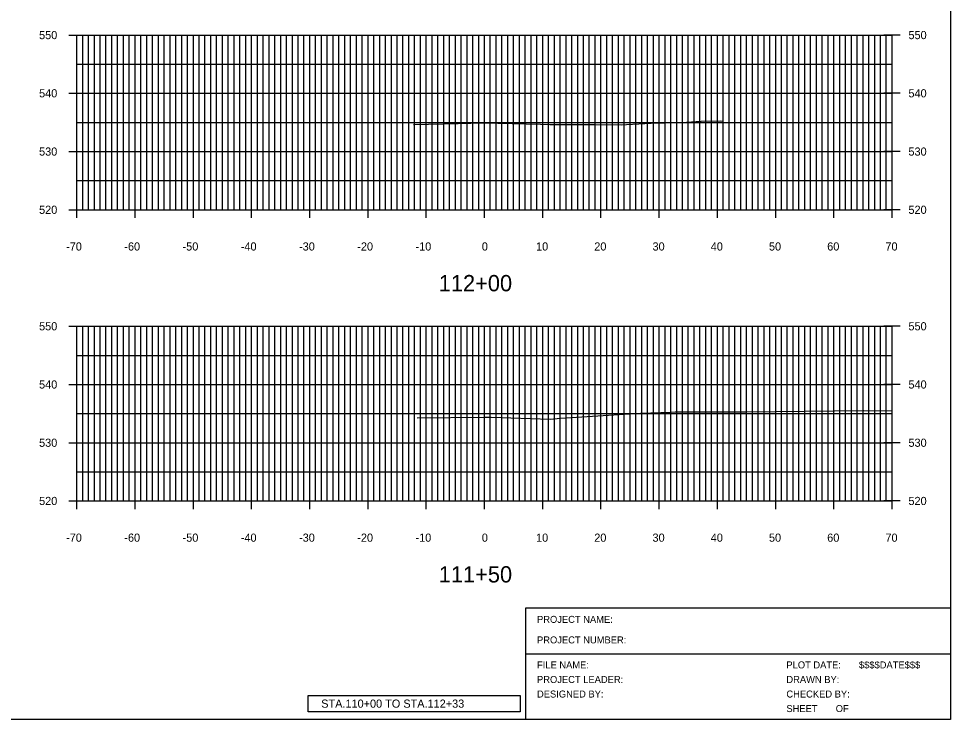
# Model space of a CAD drawing. Extents: x 1509063 to 1512863, y 401160 to 402918.
# Drawn here: x 1512702.7 to 1512862.7, y 402252.1 to 402372.4 of the extents above; entities that cross this region are included whole.
import ezdxf

# ---------------------------------------------------------------- set-up
doc = ezdxf.new("R2010")
doc.units = 0
for name, color, linetype in [('NBL1', 7, 'Continuous'), ('XAX_P', 7, 'Continuous'), ('XAXTIC_P', 7, 'Continuous'), ('XAXTXT_P_T', 7, 'Continuous'), ('XFRAME_P', 7, 'Continuous'), ('XGL_P', 7, 'Continuous'), ('XSLOG', 7, 'Continuous')]:
    doc.layers.add(name, color=color, linetype=linetype)

msp = doc.modelspace()

# ---------------------------------------------------------------- linework, layer by layer
at = {"layer": 'NBL1'}
for p, q in [((1512789.81, 402271.25), (1512862.73, 402271.25)), ((1512789.81, 402252.08), (1512789.81, 402271.25)), ((1512789.81, 402263.33), (1512862.73, 402263.33))]:
    msp.add_line(p, q, dxfattribs=at)
msp.add_lwpolyline([(1512862.73, 402252.08), (1512542.73, 402252.08), (1512542.73, 402462.08), (1512862.73, 402462.08)], close=True, dxfattribs=at)
at = {"layer": 'XAX_P'}
for p, q in [((1512712.73, 402339.58), (1512712.73, 402369.58)), ((1512782.73, 402339.58), (1512782.73, 402369.58)), ((1512852.73, 402339.58), (1512852.73, 402369.58)), ((1512712.73, 402339.58), (1512852.73, 402339.58)), ((1512712.73, 402289.58), (1512712.73, 402319.58)), ((1512782.73, 402289.58), (1512782.73, 402319.58)), ((1512852.73, 402289.58), (1512852.73, 402319.58)), ((1512712.73, 402289.58), (1512852.73, 402289.58))]:
    msp.add_line(p, q, dxfattribs=at)
at = {"layer": 'XAXTIC_P'}
for p, q in [((1512711.33, 402369.58), (1512714.13, 402369.58)), ((1512781.33, 402369.58), (1512784.13, 402369.58)), ((1512854.13, 402369.58), (1512851.33, 402369.58)), ((1512711.33, 402359.58), (1512714.13, 402359.58)), ((1512781.33, 402359.58), (1512784.13, 402359.58)), ((1512854.13, 402359.58), (1512851.33, 402359.58)), ((1512711.33, 402349.58), (1512714.13, 402349.58)), ((1512781.33, 402349.58), (1512784.13, 402349.58)), ((1512854.13, 402349.58), (1512851.33, 402349.58)), ((1512712.73, 402338.18), (1512712.73, 402340.98)), ((1512722.73, 402338.18), (1512722.73, 402340.98)), ((1512732.73, 402338.18), (1512732.73, 402340.98)), ((1512742.73, 402338.18), (1512742.73, 402340.98)), ((1512752.73, 402338.18), (1512752.73, 402340.98)), ((1512762.73, 402338.18), (1512762.73, 402340.98)), ((1512772.73, 402338.18), (1512772.73, 402340.98)), ((1512782.73, 402338.18), (1512782.73, 402340.98)), ((1512792.73, 402338.18), (1512792.73, 402340.98)), ((1512802.73, 402338.18), (1512802.73, 402340.98)), ((1512812.73, 402338.18), (1512812.73, 402340.98)), ((1512822.73, 402338.18), (1512822.73, 402340.98)), ((1512832.73, 402338.18), (1512832.73, 402340.98)), ((1512842.73, 402338.18), (1512842.73, 402340.98)), ((1512852.73, 402338.18), (1512852.73, 402340.98)), ((1512711.33, 402339.58), (1512714.13, 402339.58)), ((1512781.33, 402339.58), (1512784.13, 402339.58)), ((1512854.13, 402339.58), (1512851.33, 402339.58)), ((1512711.33, 402319.58), (1512714.13, 402319.58)), ((1512781.33, 402319.58), (1512784.13, 402319.58)), ((1512854.13, 402319.58), (1512851.33, 402319.58)), ((1512711.33, 402309.58), (1512714.13, 402309.58)), ((1512781.33, 402309.58), (1512784.13, 402309.58)), ((1512854.13, 402309.58), (1512851.33, 402309.58)), ((1512711.33, 402299.58), (1512714.13, 402299.58)), ((1512781.33, 402299.58), (1512784.13, 402299.58)), ((1512854.13, 402299.58), (1512851.33, 402299.58)), ((1512712.73, 402288.18), (1512712.73, 402290.98)), ((1512722.73, 402288.18), (1512722.73, 402290.98)), ((1512732.73, 402288.18), (1512732.73, 402290.98)), ((1512742.73, 402288.18), (1512742.73, 402290.98)), ((1512752.73, 402288.18), (1512752.73, 402290.98)), ((1512762.73, 402288.18), (1512762.73, 402290.98)), ((1512772.73, 402288.18), (1512772.73, 402290.98)), ((1512782.73, 402288.18), (1512782.73, 402290.98)), ((1512792.73, 402288.18), (1512792.73, 402290.98)), ((1512802.73, 402288.18), (1512802.73, 402290.98)), ((1512812.73, 402288.18), (1512812.73, 402290.98)), ((1512822.73, 402288.18), (1512822.73, 402290.98)), ((1512832.73, 402288.18), (1512832.73, 402290.98)), ((1512842.73, 402288.18), (1512842.73, 402290.98)), ((1512852.73, 402288.18), (1512852.73, 402290.98)), ((1512711.33, 402289.58), (1512714.13, 402289.58)), ((1512781.33, 402289.58), (1512784.13, 402289.58)), ((1512854.13, 402289.58), (1512851.33, 402289.58))]:
    msp.add_line(p, q, dxfattribs=at)
at = {"layer": 'XFRAME_P'}
msp.add_lwpolyline([(1512752.43, 402256.18), (1512788.83, 402256.18), (1512788.83, 402253.38), (1512752.43, 402253.38)], close=True, dxfattribs=at)
at = {"layer": 'XGL_P'}
for p, q in [((1512712.73, 402369.58), (1512852.73, 402369.58)), ((1512712.73, 402339.58), (1512712.73, 402369.58)), ((1512713.73, 402339.58), (1512713.73, 402369.58)), ((1512714.73, 402339.58), (1512714.73, 402369.58)), ((1512715.73, 402339.58), (1512715.73, 402369.58)), ((1512716.73, 402339.58), (1512716.73, 402369.58)), ((1512717.73, 402339.58), (1512717.73, 402369.58)), ((1512718.73, 402339.58), (1512718.73, 402369.58)), ((1512719.73, 402339.58), (1512719.73, 402369.58)), ((1512720.73, 402339.58), (1512720.73, 402369.58)), ((1512721.73, 402339.58), (1512721.73, 402369.58)), ((1512722.73, 402339.58), (1512722.73, 402369.58)), ((1512723.73, 402339.58), (1512723.73, 402369.58)), ((1512724.73, 402339.58), (1512724.73, 402369.58)), ((1512725.73, 402339.58), (1512725.73, 402369.58)), ((1512726.73, 402339.58), (1512726.73, 402369.58)), ((1512727.73, 402339.58), (1512727.73, 402369.58)), ((1512728.73, 402339.58), (1512728.73, 402369.58)), ((1512729.73, 402339.58), (1512729.73, 402369.58)), ((1512730.73, 402339.58), (1512730.73, 402369.58)), ((1512731.73, 402339.58), (1512731.73, 402369.58)), ((1512732.73, 402339.58), (1512732.73, 402369.58)), ((1512733.73, 402339.58), (1512733.73, 402369.58)), ((1512734.73, 402339.58), (1512734.73, 402369.58)), ((1512735.73, 402339.58), (1512735.73, 402369.58)), ((1512736.73, 402339.58), (1512736.73, 402369.58)), ((1512737.73, 402339.58), (1512737.73, 402369.58)), ((1512738.73, 402339.58), (1512738.73, 402369.58)), ((1512739.73, 402339.58), (1512739.73, 402369.58)), ((1512740.73, 402339.58), (1512740.73, 402369.58)), ((1512741.73, 402339.58), (1512741.73, 402369.58)), ((1512742.73, 402339.58), (1512742.73, 402369.58)), ((1512743.73, 402339.58), (1512743.73, 402369.58)), ((1512744.73, 402339.58), (1512744.73, 402369.58)), ((1512745.73, 402339.58), (1512745.73, 402369.58)), ((1512746.73, 402339.58), (1512746.73, 402369.58)), ((1512747.73, 402339.58), (1512747.73, 402369.58)), ((1512748.73, 402339.58), (1512748.73, 402369.58)), ((1512749.73, 402339.58), (1512749.73, 402369.58)), ((1512750.73, 402339.58), (1512750.73, 402369.58)), ((1512751.73, 402339.58), (1512751.73, 402369.58)), ((1512752.73, 402339.58), (1512752.73, 402369.58)), ((1512753.73, 402339.58), (1512753.73, 402369.58)), ((1512754.73, 402339.58), (1512754.73, 402369.58)), ((1512755.73, 402339.58), (1512755.73, 402369.58)), ((1512756.73, 402339.58), (1512756.73, 402369.58)), ((1512757.73, 402339.58), (1512757.73, 402369.58)), ((1512758.73, 402339.58), (1512758.73, 402369.58)), ((1512759.73, 402339.58), (1512759.73, 402369.58)), ((1512760.73, 402339.58), (1512760.73, 402369.58)), ((1512761.73, 402339.58), (1512761.73, 402369.58)), ((1512762.73, 402339.58), (1512762.73, 402369.58)), ((1512763.73, 402339.58), (1512763.73, 402369.58)), ((1512764.73, 402339.58), (1512764.73, 402369.58)), ((1512765.73, 402339.58), (1512765.73, 402369.58)), ((1512766.73, 402339.58), (1512766.73, 402369.58)), ((1512767.73, 402339.58), (1512767.73, 402369.58)), ((1512768.73, 402339.58), (1512768.73, 402369.58)), ((1512769.73, 402339.58), (1512769.73, 402369.58)), ((1512770.73, 402339.58), (1512770.73, 402369.58)), ((1512771.73, 402339.58), (1512771.73, 402369.58)), ((1512772.73, 402339.58), (1512772.73, 402369.58)), ((1512773.73, 402339.58), (1512773.73, 402369.58)), ((1512774.73, 402339.58), (1512774.73, 402369.58)), ((1512775.73, 402339.58), (1512775.73, 402369.58)), ((1512776.73, 402339.58), (1512776.73, 402369.58)), ((1512777.73, 402339.58), (1512777.73, 402369.58)), ((1512778.73, 402339.58), (1512778.73, 402369.58)), ((1512779.73, 402339.58), (1512779.73, 402369.58)), ((1512780.73, 402339.58), (1512780.73, 402369.58)), ((1512781.73, 402339.58), (1512781.73, 402369.58)), ((1512782.73, 402339.58), (1512782.73, 402369.58)), ((1512783.73, 402339.58), (1512783.73, 402369.58)), ((1512784.73, 402339.58), (1512784.73, 402369.58)), ((1512785.73, 402339.58), (1512785.73, 402369.58)), ((1512786.73, 402339.58), (1512786.73, 402369.58)), ((1512787.73, 402339.58), (1512787.73, 402369.58)), ((1512788.73, 402339.58), (1512788.73, 402369.58)), ((1512789.73, 402339.58), (1512789.73, 402369.58)), ((1512790.73, 402339.58), (1512790.73, 402369.58)), ((1512791.73, 402339.58), (1512791.73, 402369.58)), ((1512792.73, 402339.58), (1512792.73, 402369.58)), ((1512793.73, 402339.58), (1512793.73, 402369.58)), ((1512794.73, 402339.58), (1512794.73, 402369.58)), ((1512795.73, 402339.58), (1512795.73, 402369.58)), ((1512796.73, 402339.58), (1512796.73, 402369.58)), ((1512797.73, 402339.58), (1512797.73, 402369.58)), ((1512798.73, 402339.58), (1512798.73, 402369.58)), ((1512799.73, 402339.58), (1512799.73, 402369.58)), ((1512800.73, 402339.58), (1512800.73, 402369.58)), ((1512801.73, 402339.58), (1512801.73, 402369.58)), ((1512802.73, 402339.58), (1512802.73, 402369.58)), ((1512803.73, 402339.58), (1512803.73, 402369.58)), ((1512804.73, 402339.58), (1512804.73, 402369.58)), ((1512805.73, 402339.58), (1512805.73, 402369.58)), ((1512806.73, 402339.58), (1512806.73, 402369.58)), ((1512807.73, 402339.58), (1512807.73, 402369.58)), ((1512808.73, 402339.58), (1512808.73, 402369.58)), ((1512809.73, 402339.58), (1512809.73, 402369.58)), ((1512810.73, 402339.58), (1512810.73, 402369.58)), ((1512811.73, 402339.58), (1512811.73, 402369.58)), ((1512812.73, 402339.58), (1512812.73, 402369.58)), ((1512813.73, 402339.58), (1512813.73, 402369.58)), ((1512814.73, 402339.58), (1512814.73, 402369.58)), ((1512815.73, 402339.58), (1512815.73, 402369.58)), ((1512816.73, 402339.58), (1512816.73, 402369.58)), ((1512817.73, 402339.58), (1512817.73, 402369.58)), ((1512818.73, 402339.58), (1512818.73, 402369.58)), ((1512819.73, 402339.58), (1512819.73, 402369.58)), ((1512820.73, 402339.58), (1512820.73, 402369.58)), ((1512821.73, 402339.58), (1512821.73, 402369.58)), ((1512822.73, 402339.58), (1512822.73, 402369.58)), ((1512823.73, 402339.58), (1512823.73, 402369.58)), ((1512824.73, 402339.58), (1512824.73, 402369.58)), ((1512825.73, 402339.58), (1512825.73, 402369.58)), ((1512826.73, 402339.58), (1512826.73, 402369.58)), ((1512827.73, 402339.58), (1512827.73, 402369.58)), ((1512828.73, 402339.58), (1512828.73, 402369.58)), ((1512829.73, 402339.58), (1512829.73, 402369.58)), ((1512830.73, 402339.58), (1512830.73, 402369.58)), ((1512831.73, 402339.58), (1512831.73, 402369.58)), ((1512832.73, 402339.58), (1512832.73, 402369.58)), ((1512833.73, 402339.58), (1512833.73, 402369.58)), ((1512834.73, 402339.58), (1512834.73, 402369.58)), ((1512835.73, 402339.58), (1512835.73, 402369.58)), ((1512836.73, 402339.58), (1512836.73, 402369.58)), ((1512837.73, 402339.58), (1512837.73, 402369.58)), ((1512838.73, 402339.58), (1512838.73, 402369.58)), ((1512839.73, 402339.58), (1512839.73, 402369.58)), ((1512840.73, 402339.58), (1512840.73, 402369.58)), ((1512841.73, 402339.58), (1512841.73, 402369.58)), ((1512842.73, 402339.58), (1512842.73, 402369.58)), ((1512843.73, 402339.58), (1512843.73, 402369.58)), ((1512844.73, 402339.58), (1512844.73, 402369.58)), ((1512845.73, 402339.58), (1512845.73, 402369.58)), ((1512846.73, 402339.58), (1512846.73, 402369.58)), ((1512847.73, 402339.58), (1512847.73, 402369.58)), ((1512848.73, 402339.58), (1512848.73, 402369.58)), ((1512849.73, 402339.58), (1512849.73, 402369.58)), ((1512850.73, 402339.58), (1512850.73, 402369.58)), ((1512851.73, 402339.58), (1512851.73, 402369.58)), ((1512852.73, 402339.58), (1512852.73, 402369.58)), ((1512712.73, 402364.58), (1512852.73, 402364.58)), ((1512712.73, 402359.58), (1512852.73, 402359.58)), ((1512712.73, 402354.58), (1512852.73, 402354.58)), ((1512712.73, 402349.58), (1512852.73, 402349.58)), ((1512712.73, 402344.58), (1512852.73, 402344.58)), ((1512712.73, 402339.58), (1512852.73, 402339.58)), ((1512712.73, 402319.58), (1512852.73, 402319.58)), ((1512712.73, 402289.58), (1512712.73, 402319.58)), ((1512713.73, 402289.58), (1512713.73, 402319.58)), ((1512714.73, 402289.58), (1512714.73, 402319.58)), ((1512715.73, 402289.58), (1512715.73, 402319.58)), ((1512716.73, 402289.58), (1512716.73, 402319.58)), ((1512717.73, 402289.58), (1512717.73, 402319.58)), ((1512718.73, 402289.58), (1512718.73, 402319.58)), ((1512719.73, 402289.58), (1512719.73, 402319.58)), ((1512720.73, 402289.58), (1512720.73, 402319.58)), ((1512721.73, 402289.58), (1512721.73, 402319.58)), ((1512722.73, 402289.58), (1512722.73, 402319.58)), ((1512723.73, 402289.58), (1512723.73, 402319.58)), ((1512724.73, 402289.58), (1512724.73, 402319.58)), ((1512725.73, 402289.58), (1512725.73, 402319.58)), ((1512726.73, 402289.58), (1512726.73, 402319.58)), ((1512727.73, 402289.58), (1512727.73, 402319.58)), ((1512728.73, 402289.58), (1512728.73, 402319.58)), ((1512729.73, 402289.58), (1512729.73, 402319.58)), ((1512730.73, 402289.58), (1512730.73, 402319.58)), ((1512731.73, 402289.58), (1512731.73, 402319.58)), ((1512732.73, 402289.58), (1512732.73, 402319.58)), ((1512733.73, 402289.58), (1512733.73, 402319.58)), ((1512734.73, 402289.58), (1512734.73, 402319.58)), ((1512735.73, 402289.58), (1512735.73, 402319.58)), ((1512736.73, 402289.58), (1512736.73, 402319.58)), ((1512737.73, 402289.58), (1512737.73, 402319.58)), ((1512738.73, 402289.58), (1512738.73, 402319.58)), ((1512739.73, 402289.58), (1512739.73, 402319.58)), ((1512740.73, 402289.58), (1512740.73, 402319.58)), ((1512741.73, 402289.58), (1512741.73, 402319.58)), ((1512742.73, 402289.58), (1512742.73, 402319.58)), ((1512743.73, 402289.58), (1512743.73, 402319.58)), ((1512744.73, 402289.58), (1512744.73, 402319.58)), ((1512745.73, 402289.58), (1512745.73, 402319.58)), ((1512746.73, 402289.58), (1512746.73, 402319.58)), ((1512747.73, 402289.58), (1512747.73, 402319.58)), ((1512748.73, 402289.58), (1512748.73, 402319.58)), ((1512749.73, 402289.58), (1512749.73, 402319.58)), ((1512750.73, 402289.58), (1512750.73, 402319.58)), ((1512751.73, 402289.58), (1512751.73, 402319.58)), ((1512752.73, 402289.58), (1512752.73, 402319.58)), ((1512753.73, 402289.58), (1512753.73, 402319.58)), ((1512754.73, 402289.58), (1512754.73, 402319.58)), ((1512755.73, 402289.58), (1512755.73, 402319.58)), ((1512756.73, 402289.58), (1512756.73, 402319.58)), ((1512757.73, 402289.58), (1512757.73, 402319.58)), ((1512758.73, 402289.58), (1512758.73, 402319.58)), ((1512759.73, 402289.58), (1512759.73, 402319.58)), ((1512760.73, 402289.58), (1512760.73, 402319.58)), ((1512761.73, 402289.58), (1512761.73, 402319.58)), ((1512762.73, 402289.58), (1512762.73, 402319.58)), ((1512763.73, 402289.58), (1512763.73, 402319.58)), ((1512764.73, 402289.58), (1512764.73, 402319.58)), ((1512765.73, 402289.58), (1512765.73, 402319.58)), ((1512766.73, 402289.58), (1512766.73, 402319.58)), ((1512767.73, 402289.58), (1512767.73, 402319.58)), ((1512768.73, 402289.58), (1512768.73, 402319.58)), ((1512769.73, 402289.58), (1512769.73, 402319.58)), ((1512770.73, 402289.58), (1512770.73, 402319.58)), ((1512771.73, 402289.58), (1512771.73, 402319.58)), ((1512772.73, 402289.58), (1512772.73, 402319.58)), ((1512773.73, 402289.58), (1512773.73, 402319.58)), ((1512774.73, 402289.58), (1512774.73, 402319.58)), ((1512775.73, 402289.58), (1512775.73, 402319.58)), ((1512776.73, 402289.58), (1512776.73, 402319.58)), ((1512777.73, 402289.58), (1512777.73, 402319.58)), ((1512778.73, 402289.58), (1512778.73, 402319.58)), ((1512779.73, 402289.58), (1512779.73, 402319.58)), ((1512780.73, 402289.58), (1512780.73, 402319.58)), ((1512781.73, 402289.58), (1512781.73, 402319.58)), ((1512782.73, 402289.58), (1512782.73, 402319.58)), ((1512783.73, 402289.58), (1512783.73, 402319.58)), ((1512784.73, 402289.58), (1512784.73, 402319.58)), ((1512785.73, 402289.58), (1512785.73, 402319.58)), ((1512786.73, 402289.58), (1512786.73, 402319.58)), ((1512787.73, 402289.58), (1512787.73, 402319.58)), ((1512788.73, 402289.58), (1512788.73, 402319.58)), ((1512789.73, 402289.58), (1512789.73, 402319.58)), ((1512790.73, 402289.58), (1512790.73, 402319.58)), ((1512791.73, 402289.58), (1512791.73, 402319.58)), ((1512792.73, 402289.58), (1512792.73, 402319.58)), ((1512793.73, 402289.58), (1512793.73, 402319.58)), ((1512794.73, 402289.58), (1512794.73, 402319.58)), ((1512795.73, 402289.58), (1512795.73, 402319.58)), ((1512796.73, 402289.58), (1512796.73, 402319.58)), ((1512797.73, 402289.58), (1512797.73, 402319.58)), ((1512798.73, 402289.58), (1512798.73, 402319.58)), ((1512799.73, 402289.58), (1512799.73, 402319.58)), ((1512800.73, 402289.58), (1512800.73, 402319.58)), ((1512801.73, 402289.58), (1512801.73, 402319.58)), ((1512802.73, 402289.58), (1512802.73, 402319.58)), ((1512803.73, 402289.58), (1512803.73, 402319.58)), ((1512804.73, 402289.58), (1512804.73, 402319.58)), ((1512805.73, 402289.58), (1512805.73, 402319.58)), ((1512806.73, 402289.58), (1512806.73, 402319.58)), ((1512807.73, 402289.58), (1512807.73, 402319.58)), ((1512808.73, 402289.58), (1512808.73, 402319.58)), ((1512809.73, 402289.58), (1512809.73, 402319.58)), ((1512810.73, 402289.58), (1512810.73, 402319.58)), ((1512811.73, 402289.58), (1512811.73, 402319.58)), ((1512812.73, 402289.58), (1512812.73, 402319.58)), ((1512813.73, 402289.58), (1512813.73, 402319.58)), ((1512814.73, 402289.58), (1512814.73, 402319.58)), ((1512815.73, 402289.58), (1512815.73, 402319.58)), ((1512816.73, 402289.58), (1512816.73, 402319.58)), ((1512817.73, 402289.58), (1512817.73, 402319.58)), ((1512818.73, 402289.58), (1512818.73, 402319.58)), ((1512819.73, 402289.58), (1512819.73, 402319.58)), ((1512820.73, 402289.58), (1512820.73, 402319.58)), ((1512821.73, 402289.58), (1512821.73, 402319.58)), ((1512822.73, 402289.58), (1512822.73, 402319.58)), ((1512823.73, 402289.58), (1512823.73, 402319.58)), ((1512824.73, 402289.58), (1512824.73, 402319.58)), ((1512825.73, 402289.58), (1512825.73, 402319.58)), ((1512826.73, 402289.58), (1512826.73, 402319.58)), ((1512827.73, 402289.58), (1512827.73, 402319.58)), ((1512828.73, 402289.58), (1512828.73, 402319.58)), ((1512829.73, 402289.58), (1512829.73, 402319.58)), ((1512830.73, 402289.58), (1512830.73, 402319.58)), ((1512831.73, 402289.58), (1512831.73, 402319.58)), ((1512832.73, 402289.58), (1512832.73, 402319.58)), ((1512833.73, 402289.58), (1512833.73, 402319.58)), ((1512834.73, 402289.58), (1512834.73, 402319.58)), ((1512835.73, 402289.58), (1512835.73, 402319.58)), ((1512836.73, 402289.58), (1512836.73, 402319.58)), ((1512837.73, 402289.58), (1512837.73, 402319.58)), ((1512838.73, 402289.58), (1512838.73, 402319.58)), ((1512839.73, 402289.58), (1512839.73, 402319.58)), ((1512840.73, 402289.58), (1512840.73, 402319.58)), ((1512841.73, 402289.58), (1512841.73, 402319.58)), ((1512842.73, 402289.58), (1512842.73, 402319.58)), ((1512843.73, 402289.58), (1512843.73, 402319.58)), ((1512844.73, 402289.58), (1512844.73, 402319.58)), ((1512845.73, 402289.58), (1512845.73, 402319.58)), ((1512846.73, 402289.58), (1512846.73, 402319.58)), ((1512847.73, 402289.58), (1512847.73, 402319.58)), ((1512848.73, 402289.58), (1512848.73, 402319.58)), ((1512849.73, 402289.58), (1512849.73, 402319.58)), ((1512850.73, 402289.58), (1512850.73, 402319.58)), ((1512851.73, 402289.58), (1512851.73, 402319.58)), ((1512852.73, 402289.58), (1512852.73, 402319.58)), ((1512712.73, 402314.58), (1512852.73, 402314.58)), ((1512712.73, 402309.58), (1512852.73, 402309.58)), ((1512712.73, 402304.58), (1512852.73, 402304.58)), ((1512712.73, 402299.58), (1512852.73, 402299.58)), ((1512712.73, 402294.58), (1512852.73, 402294.58)), ((1512712.73, 402289.58), (1512852.73, 402289.58))]:
    msp.add_line(p, q, dxfattribs=at)
at = {"layer": 'XSLOG'}
for points in [[(1512770.52, 402354.23), (1512778.21, 402354.4), (1512782.55, 402354.5), (1512792.33, 402354.28), (1512793.94, 402354.25), (1512801.64, 402354.2), (1512806.31, 402354.16), (1512807.13, 402354.23), (1512811.37, 402354.44), (1512813.61, 402354.52), (1512817.42, 402354.64), (1512819.94, 402354.77), (1512823.26, 402354.88), (1512823.63, 402354.79)], [(1512771.16, 402303.88), (1512782.69, 402303.98), (1512782.89, 402303.98), (1512783.85, 402303.95), (1512794, 402303.64), (1512795.8, 402303.79), (1512809.49, 402304.66), (1512814.81, 402304.85), (1512815.49, 402304.9), (1512825.18, 402304.87), (1512827.79, 402304.86), (1512847.87, 402305.09), (1512852.73, 402305.07)]]:
    msp.add_lwpolyline(points, dxfattribs=at)

# ---------------------------------------------------------------- texts
at = {"layer": 'NBL1'}
for s, p in [('PROJECT NAME:', (1512791.75, 402268.65)), ('PROJECT NUMBER:', (1512791.75, 402265.12)), ('FILE NAME:', (1512791.75, 402260.83)), ('PLOT DATE:', (1512834.57, 402260.83)), ('$$$$DATE$$$', (1512847.03, 402260.83)), ('PROJECT LEADER:', (1512791.75, 402258.33)), ('DRAWN BY:', (1512834.57, 402258.33)), ('DESIGNED BY:', (1512791.75, 402255.83)), ('CHECKED BY:', (1512834.57, 402255.83)), ('SHEET       OF', (1512834.57, 402253.33))]:
    msp.add_text(s, height=1.2, rotation=360, dxfattribs=at).set_placement(p)
at = {"layer": 'XAXTXT_P_T'}
for s, height, p in [('550', 1.4, (1512706.24, 402368.88)), ('550', 1.4, (1512855.53, 402368.88)), ('540', 1.4, (1512706.24, 402358.88)), ('540', 1.4, (1512855.53, 402358.88)), ('530', 1.4, (1512706.24, 402348.88)), ('530', 1.4, (1512855.53, 402348.88)), ('520', 1.4, (1512706.24, 402338.88)), ('520', 1.4, (1512855.53, 402338.88)), ('-70', 1.4, (1512710.88, 402332.58)), ('-60', 1.4, (1512720.88, 402332.58)), ('-50', 1.4, (1512730.88, 402332.58)), ('-40', 1.4, (1512740.88, 402332.58)), ('-30', 1.4, (1512750.88, 402332.58)), ('-20', 1.4, (1512760.88, 402332.58)), ('-10', 1.4, (1512770.88, 402332.58)), ('0', 1.4, (1512782.27, 402332.58)), ('10', 1.4, (1512791.58, 402332.58)), ('20', 1.4, (1512801.58, 402332.58)), ('30', 1.4, (1512811.58, 402332.58)), ('40', 1.4, (1512821.58, 402332.58)), ('50', 1.4, (1512831.58, 402332.58)), ('60', 1.4, (1512841.58, 402332.58)), ('70', 1.4, (1512851.58, 402332.58)), ('112+00', 2.8, (1512774.87, 402325.58)), ('550', 1.4, (1512706.24, 402318.88)), ('550', 1.4, (1512855.53, 402318.88)), ('540', 1.4, (1512706.24, 402308.88)), ('540', 1.4, (1512855.53, 402308.88)), ('530', 1.4, (1512706.24, 402298.88)), ('530', 1.4, (1512855.53, 402298.88)), ('520', 1.4, (1512706.24, 402288.88)), ('520', 1.4, (1512855.53, 402288.88)), ('-70', 1.4, (1512710.88, 402282.58)), ('-60', 1.4, (1512720.88, 402282.58)), ('-50', 1.4, (1512730.88, 402282.58)), ('-40', 1.4, (1512740.88, 402282.58)), ('-30', 1.4, (1512750.88, 402282.58)), ('-20', 1.4, (1512760.88, 402282.58)), ('-10', 1.4, (1512770.88, 402282.58)), ('0', 1.4, (1512782.27, 402282.58)), ('10', 1.4, (1512791.58, 402282.58)), ('20', 1.4, (1512801.58, 402282.58)), ('30', 1.4, (1512811.58, 402282.58)), ('40', 1.4, (1512821.58, 402282.58)), ('50', 1.4, (1512831.58, 402282.58)), ('60', 1.4, (1512841.58, 402282.58)), ('70', 1.4, (1512851.58, 402282.58)), ('111+50', 2.8, (1512774.87, 402275.58))]:
    msp.add_text(s, height=height, dxfattribs=at).set_placement(p)
at = {"layer": 'XFRAME_P'}
msp.add_text('STA.110+00 TO STA.112+33', height=1.4, dxfattribs=at).set_placement((1512754.69, 402254.08))

doc.saveas('drawing.dxf')
